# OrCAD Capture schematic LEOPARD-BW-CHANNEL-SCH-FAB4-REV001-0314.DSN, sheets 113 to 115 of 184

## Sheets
113 058_DDR4 DIMM CPU0 CHD-1: size A3; title: DDR4 DIMM CPU0 CHD-1
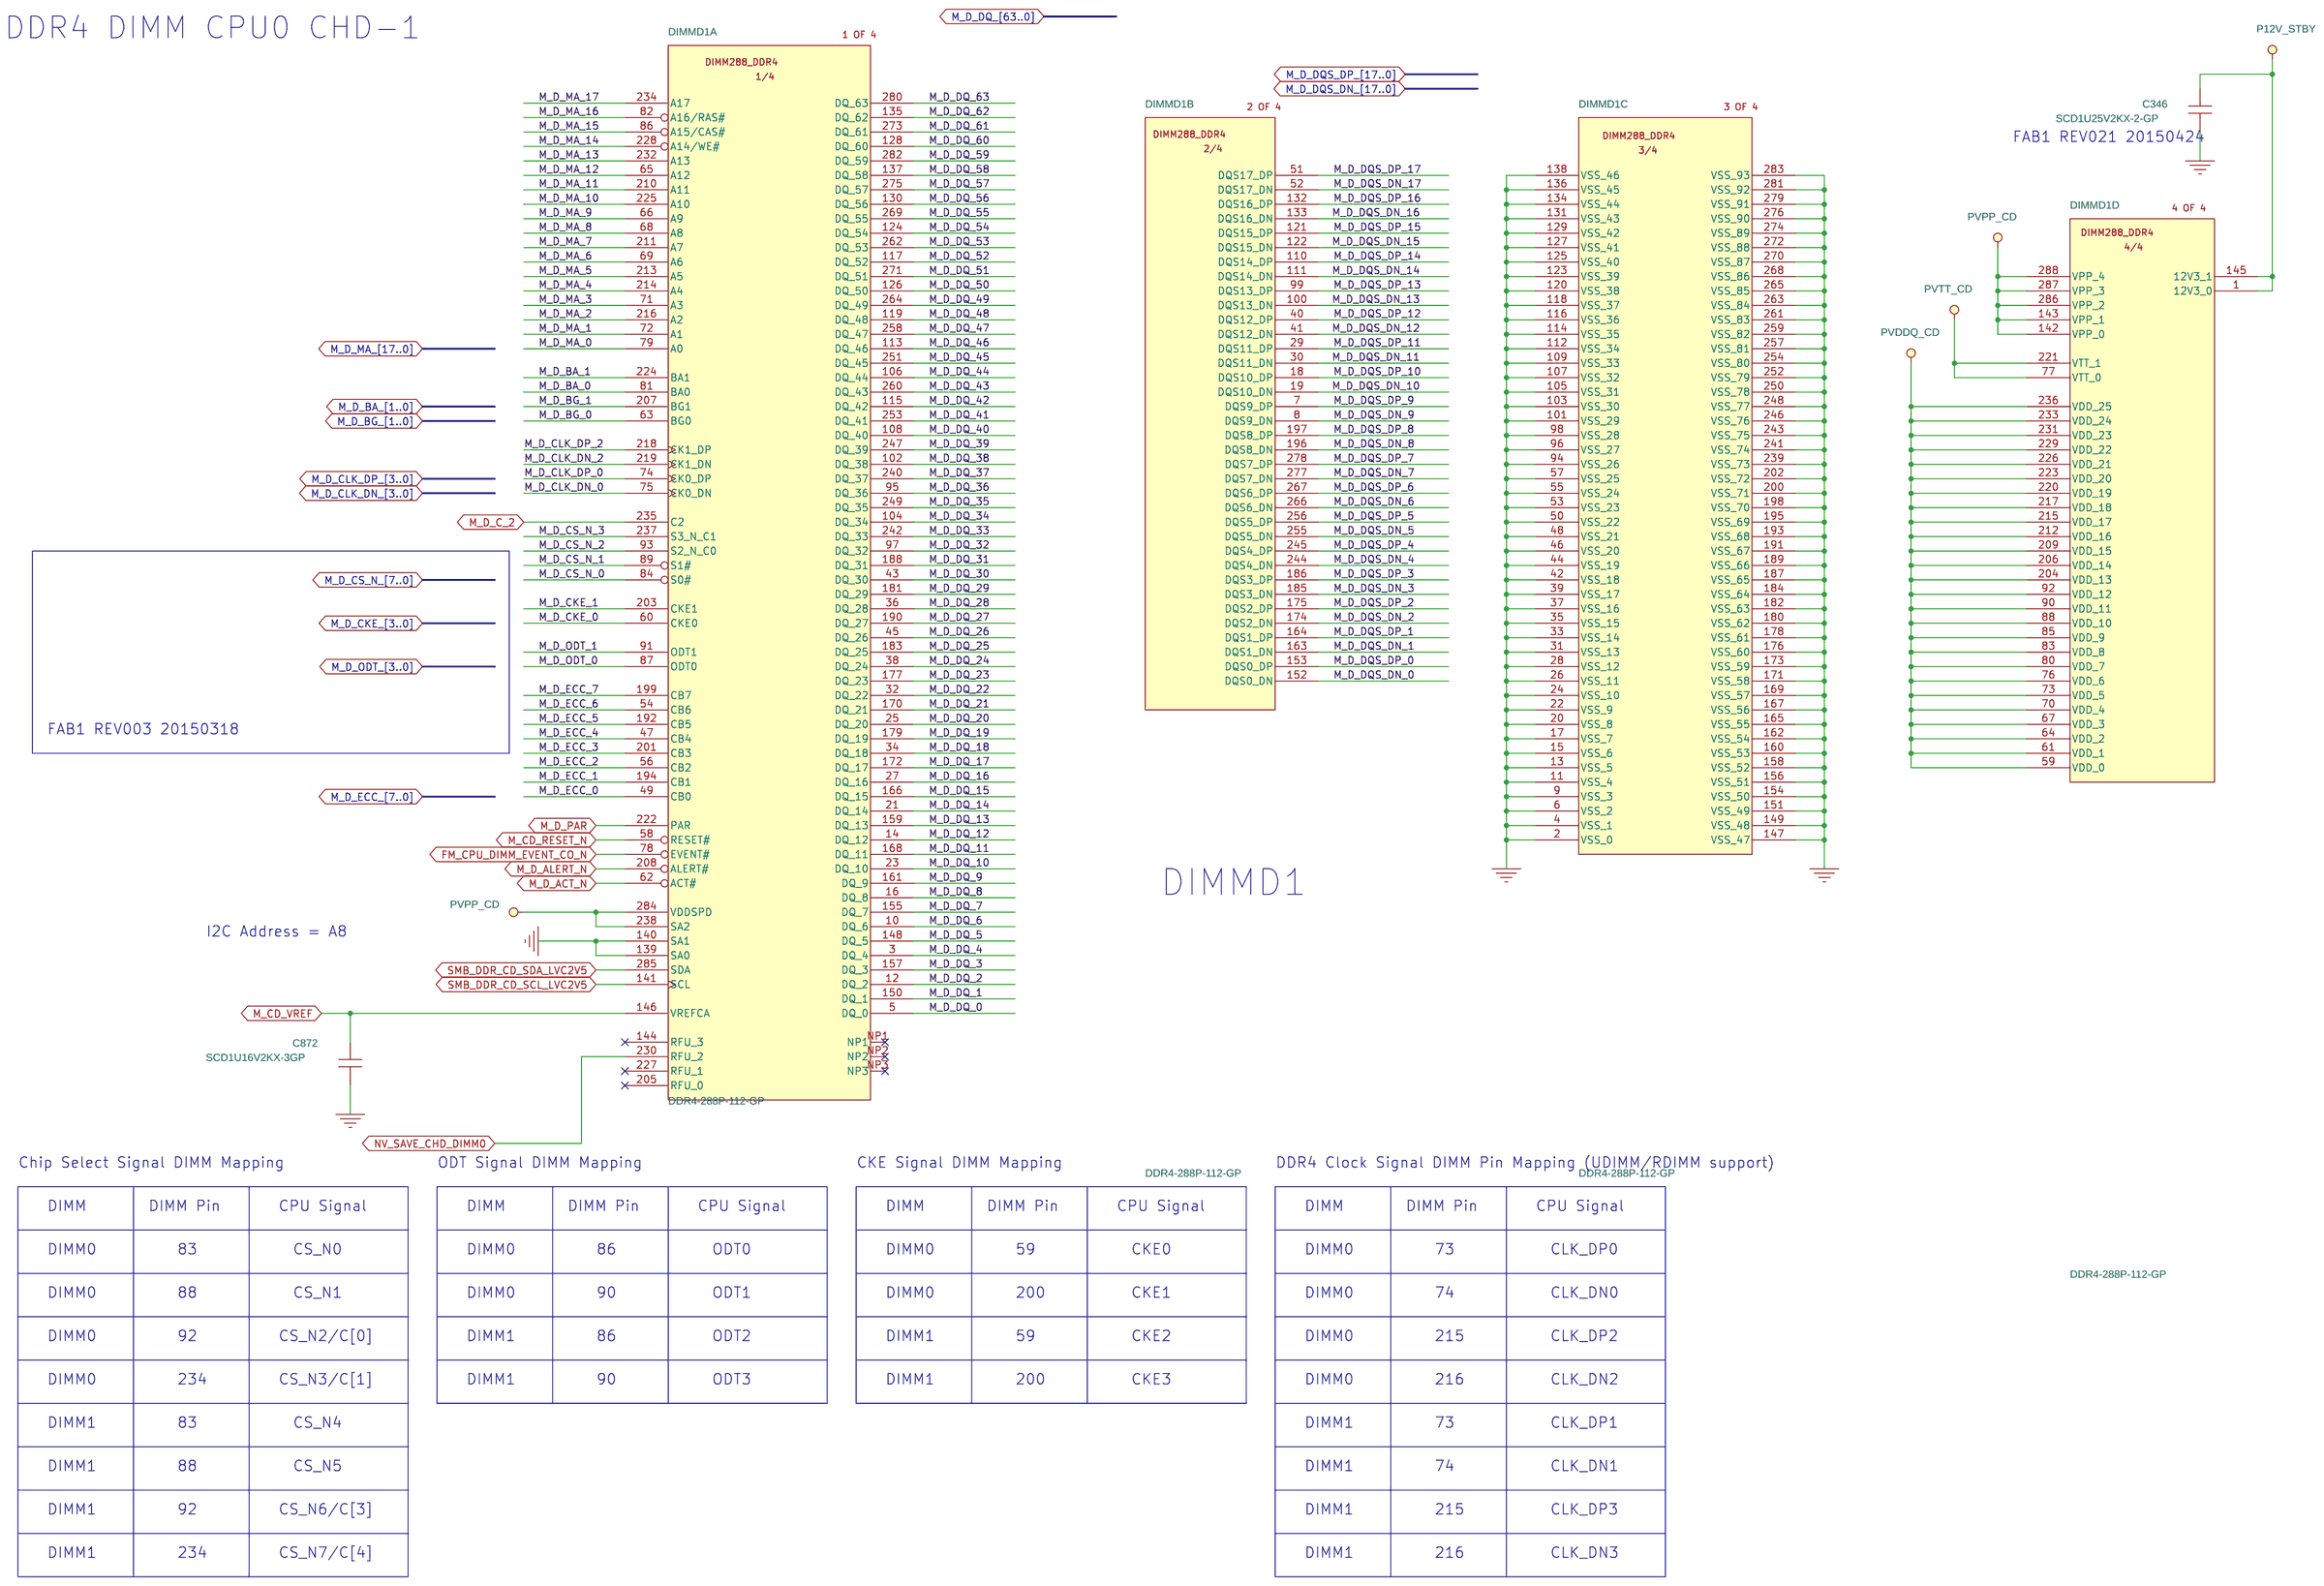
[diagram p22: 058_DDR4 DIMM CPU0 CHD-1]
114 057_DDR4 DIMM CPU0 CHC-2: size A3; title: DDR4 DIMM CPU0 CHC-2
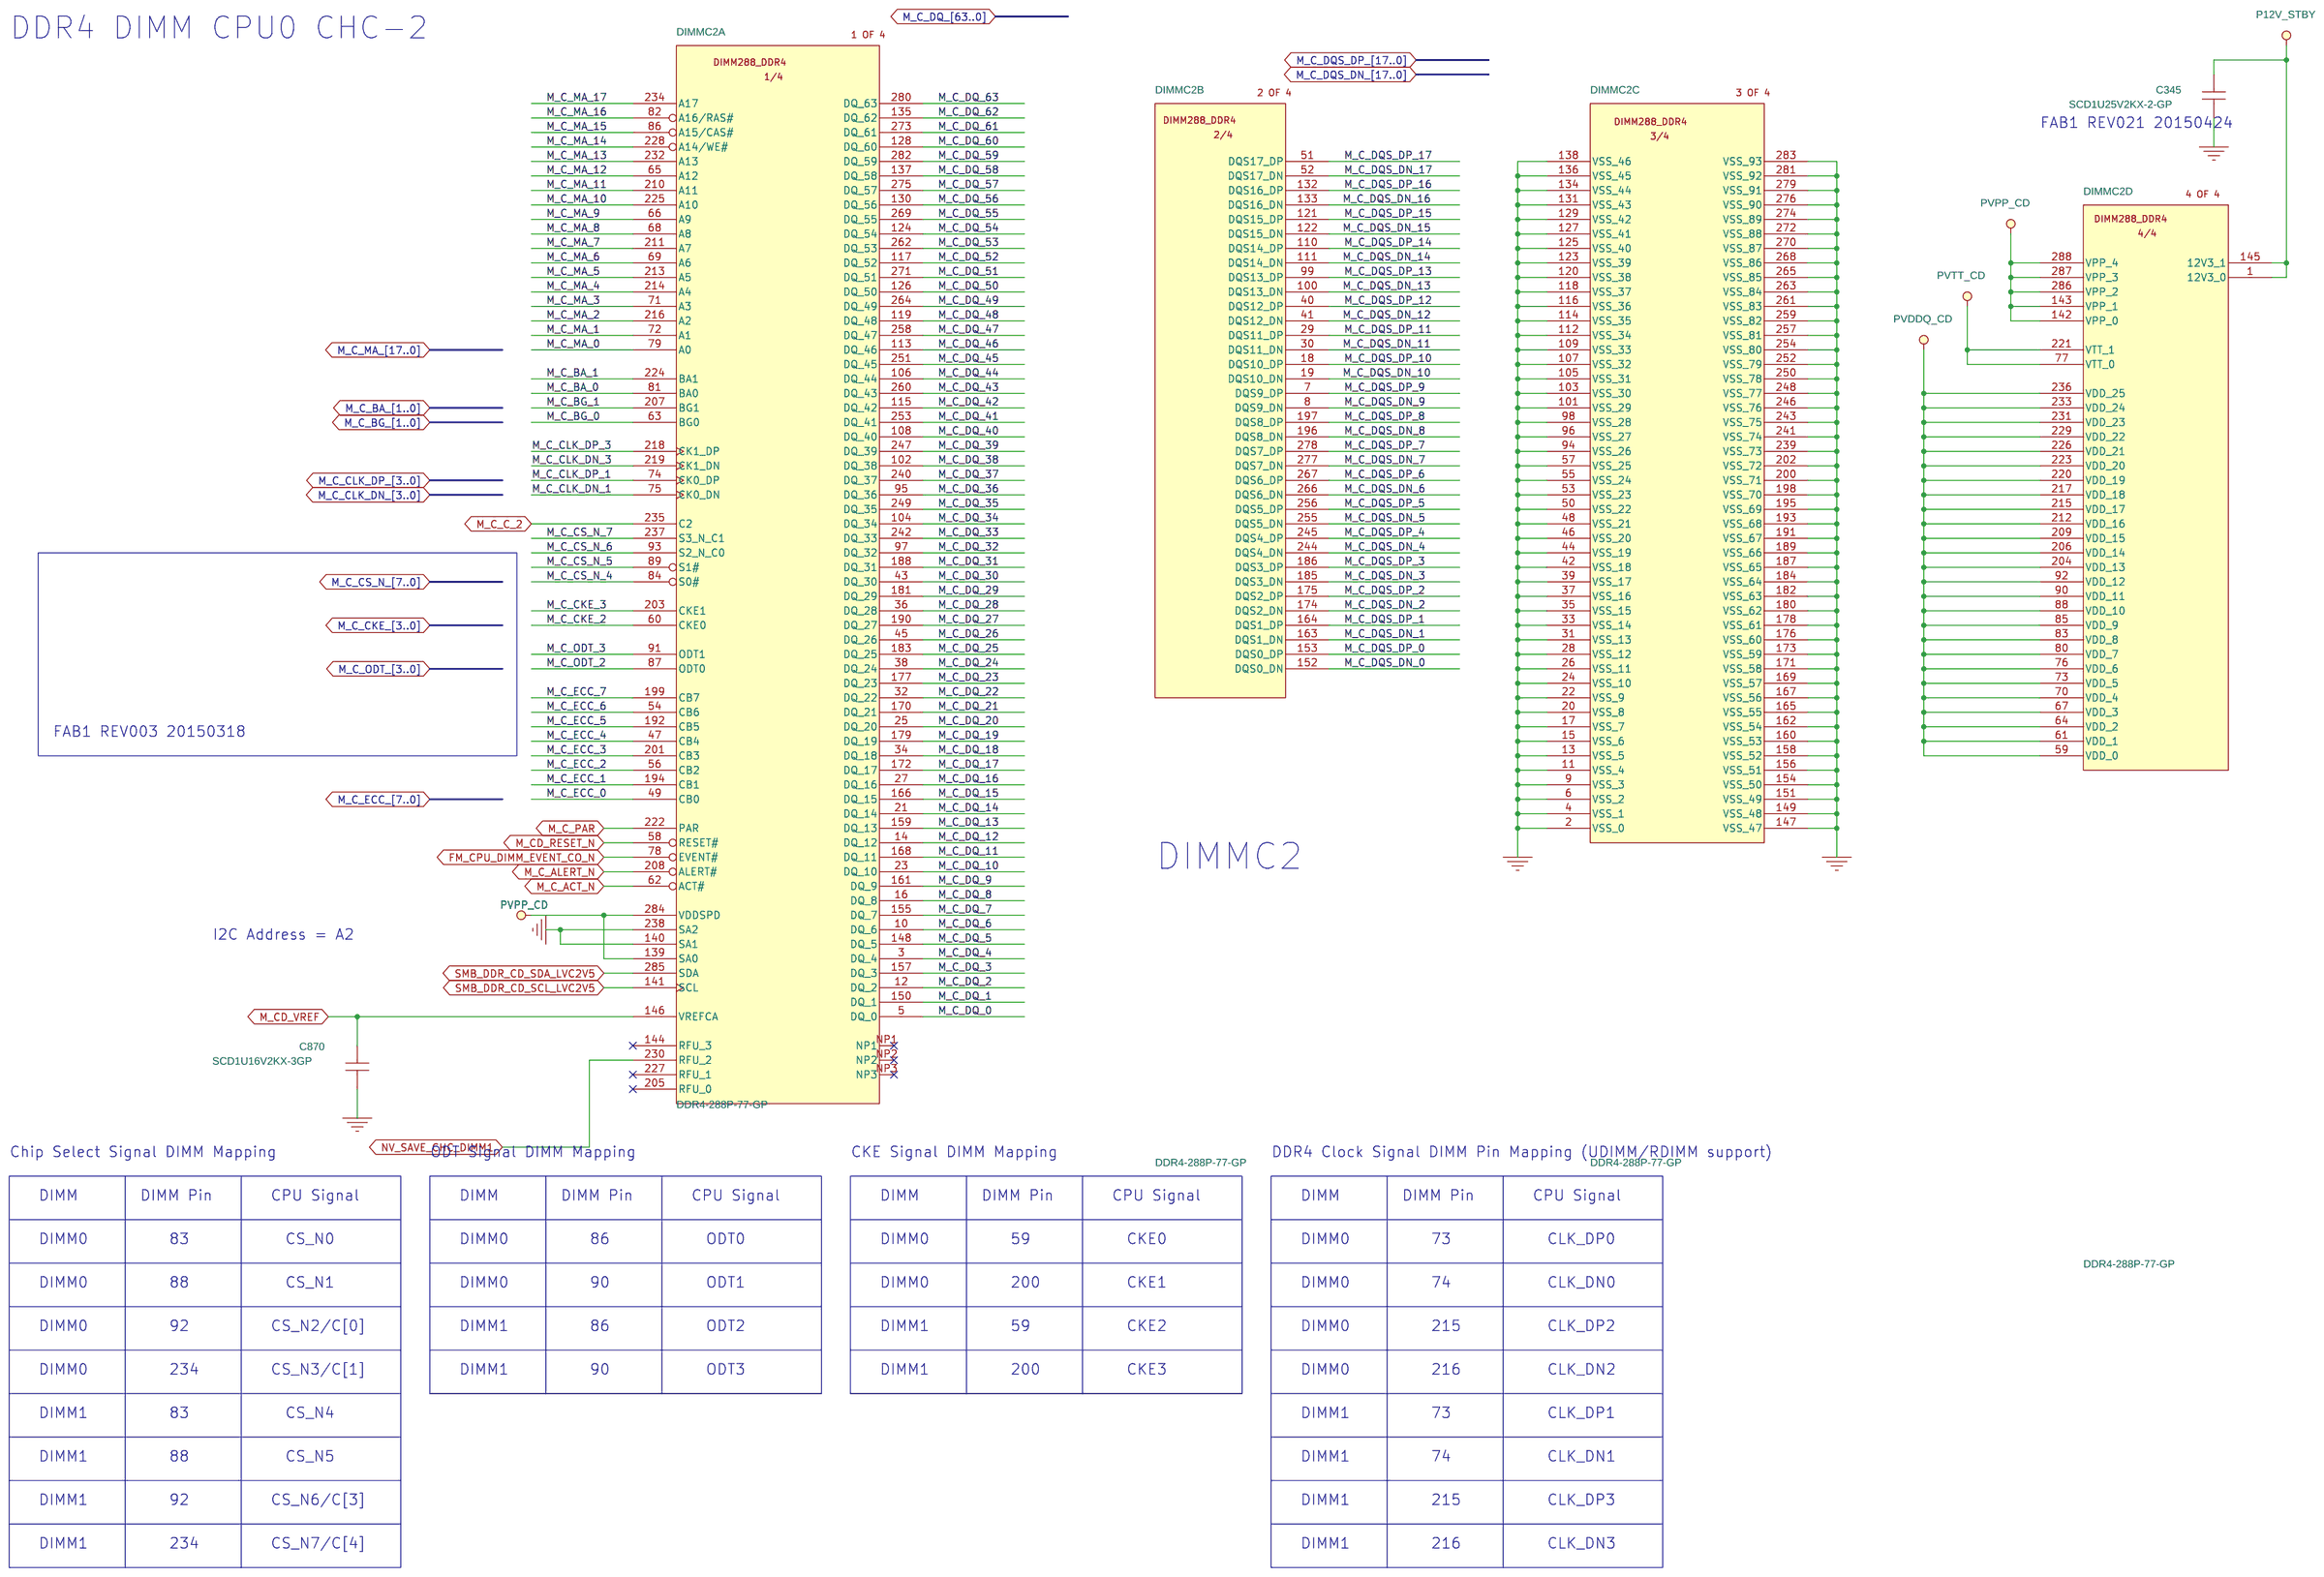
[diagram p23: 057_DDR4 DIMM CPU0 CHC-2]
115 056_DDR4 DIMM CPU0 CHC-1: size A3; title: DDR4 DIMM CPU0 CHC-1
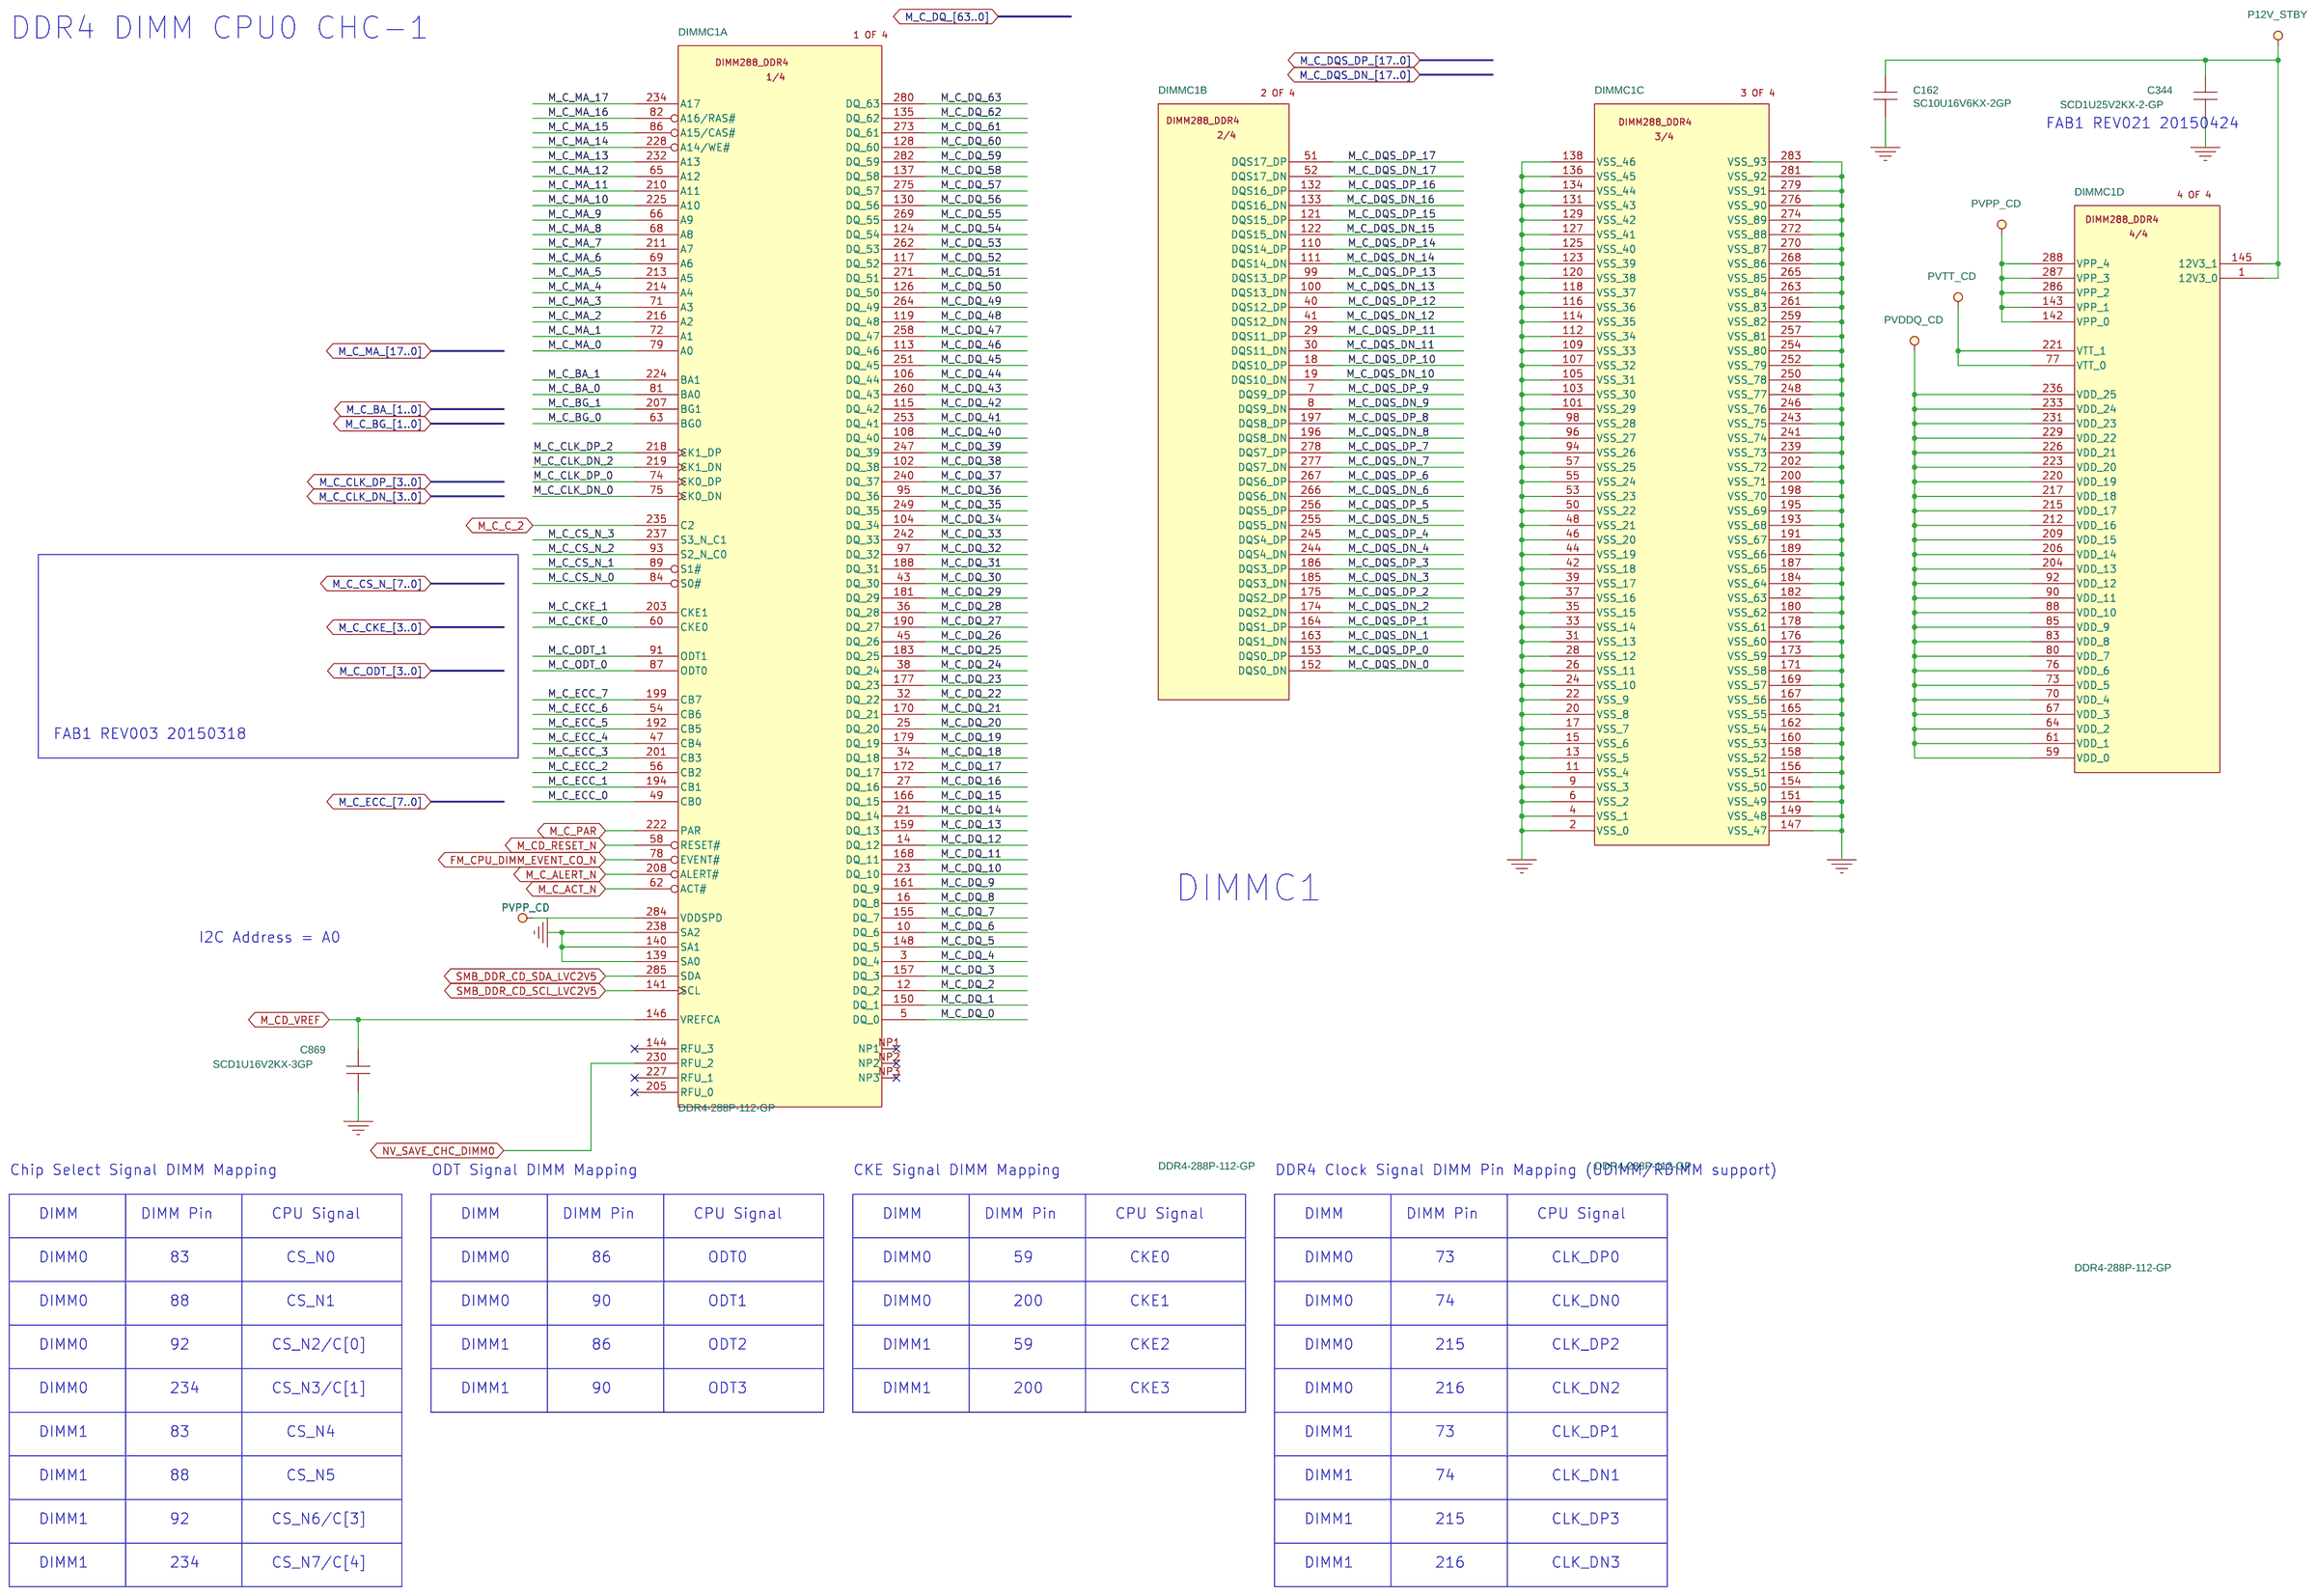
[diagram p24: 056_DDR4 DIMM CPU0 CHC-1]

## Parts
sheet 056_DDR4 DIMM CPU0 CHC-1
C162  SC10U16V6KX-2GP  [C1206H71]
C344  SCD1U25V2KX-2-GP  [C402H22]
C869  SCD1U16V2KX-3GP  [C402H22]
DIMMC1  DDR4-288P-112-GP  [10124632-0001113LF]  (sections A,B,C,D)
sheet 057_DDR4 DIMM CPU0 CHC-2
C345  SCD1U25V2KX-2-GP  [C402H22]
C870  SCD1U16V2KX-3GP  [C402H22]
DIMMC2  DDR4-288P-77-GP  [10124632-0001113LF]  (sections A,B,C,D)
sheet 058_DDR4 DIMM CPU0 CHD-1
C346  SCD1U25V2KX-2-GP  [C402H22]
C872  SCD1U16V2KX-3GP  [C402H22]
DIMMD1  DDR4-288P-112-GP  [10124632-0001113LF]  (sections A,B,C,D)

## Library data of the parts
C162 = SC10U16V6KX-2GP: CHIP CAP C 10U 16V K1206 X7R; GREENDFACTOR: R2_SA;HF_SA;G_SA;; Part Number: 78.10621.22L; Part Type: SMD-BCG; SPEC: http://wpqssvr.wistron.com.tw:7001/wpqs/servlet/COM.qpart.Attachment?PartNumber=78.10621.22L
C344-C346 = SCD1U25V2KX-2-GP: CHIP CAP C 0.1U 25V K0402 X7R; GREENDFACTOR: R2_SA;HF_SA;G_SA;; Part Number: 78.10422.2FL; Part Type: SMD-BCG4; SPEC: http://wpqssvr.wistron.com.tw:7001/wpqs/servlet/COM.qpart.Attachment?PartNumber=78.10422.2FL
C869 C870 C872 = SCD1U16V2KX-3GP: CHIP CAP C 0.1U 16V K0402 X7R; CATEGORIES: CAP_1.xV; GREENDFACTOR: R2_SA;HF_SA;G_SA;; MAIN_SOURCE: M; Part Number: 78.10421.2FL; Part Type: SMD-BCG; SPEC: http://wpqssvr.wistron.com.tw:7001/wpqs/servlet/COM.qpart.Attachment?PartNumber=78.10421.2FL
DIMMC1 DIMMD1 = DDR4-288P-112-GP: SKT DIMM DDR4 288P 10124632-0003001LF; GREENDFACTOR: R2_C;; POP?: 022.10010.0E11; Part Number: 022.10010.0B91; Part Type: SOCKET-G2; SPEC: http://wpqssvr.wistron.com.tw:7001/wpqs/servlet/COM.qpart.Attachment?PartNumber=022.10010.0B91
DIMMC2 = DDR4-288P-77-GP: SKT DIMM DDR4 288P 10124632-0001001LF; GREENDFACTOR: R2_SA;; POP?: 022.10010.0B11; Part Number: 22.10244.1A1; Part Type: SOCKET-G1; SPEC: http://wpqssvr.wistron.com.tw:7001/wpqs/servlet/COM.qpart.Attachment?PartNumber=22.10244.1A1

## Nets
GND: C162.2 C344.2 C345.2 C346.2 C869.2 C870.2 C872.2 DIMMC1.2(VSS_0) DIMMC1.4(VSS_1) DIMMC1.6(VSS_2) DIMMC1.9(VSS_3) DIMMC1.11(VSS_4) DIMMC1.13(VSS_5) DIMMC1.15(VSS_6) DIMMC1.17(VSS_7) DIMMC1.20(VSS_8) DIMMC1.22(VSS_9) DIMMC1.24(VSS_10) DIMMC1.26(VSS_11) DIMMC1.28(VSS_12) DIMMC1.31(VSS_13) DIMMC1.33(VSS_14) DIMMC1.35(VSS_15) DIMMC1.37(VSS_16) DIMMC1.39(VSS_17) DIMMC1.42(VSS_18) DIMMC1.44(VSS_19) DIMMC1.46(VSS_20) DIMMC1.48(VSS_21) DIMMC1.50(VSS_22) DIMMC1.53(VSS_23) DIMMC1.55(VSS_24) DIMMC1.57(VSS_25) DIMMC1.94(VSS_26) DIMMC1.96(VSS_27) DIMMC1.98(VSS_28) DIMMC1.101(VSS_29) DIMMC1.103(VSS_30) DIMMC1.105(VSS_31) DIMMC1.107(VSS_32) DIMMC1.109(VSS_33) DIMMC1.112(VSS_34) DIMMC1.114(VSS_35) DIMMC1.116(VSS_36) DIMMC1.118(VSS_37) DIMMC1.120(VSS_38) DIMMC1.123(VSS_39) DIMMC1.125(VSS_40) DIMMC1.127(VSS_41) DIMMC1.129(VSS_42) DIMMC1.131(VSS_43) DIMMC1.134(VSS_44) DIMMC1.136(VSS_45) DIMMC1.138(VSS_46) DIMMC1.139(SA0) DIMMC1.140(SA1) DIMMC1.147(VSS_47) DIMMC1.149(VSS_48) DIMMC1.151(VSS_49) DIMMC1.154(VSS_50) DIMMC1.156(VSS_51) DIMMC1.158(VSS_52) DIMMC1.160(VSS_53) DIMMC1.162(VSS_54) DIMMC1.165(VSS_55) DIMMC1.167(VSS_56) DIMMC1.169(VSS_57) DIMMC1.171(VSS_58) DIMMC1.173(VSS_59) DIMMC1.176(VSS_60) DIMMC1.178(VSS_61) DIMMC1.180(VSS_62) DIMMC1.182(VSS_63) DIMMC1.184(VSS_64) DIMMC1.187(VSS_65) DIMMC1.189(VSS_66) DIMMC1.191(VSS_67) DIMMC1.193(VSS_68) DIMMC1.195(VSS_69) DIMMC1.198(VSS_70) DIMMC1.200(VSS_71) DIMMC1.202(VSS_72) DIMMC1.238(SA2) DIMMC1.239(VSS_73) DIMMC1.241(VSS_74) DIMMC1.243(VSS_75) DIMMC1.246(VSS_76) DIMMC1.248(VSS_77) DIMMC1.250(VSS_78) DIMMC1.252(VSS_79) DIMMC1.254(VSS_80) DIMMC1.257(VSS_81) DIMMC1.259(VSS_82) DIMMC1.261(VSS_83) DIMMC1.263(VSS_84) DIMMC1.265(VSS_85) DIMMC1.268(VSS_86) DIMMC1.270(VSS_87) DIMMC1.272(VSS_88) DIMMC1.274(VSS_89) DIMMC1.276(VSS_90) DIMMC1.279(VSS_91) DIMMC1.281(VSS_92) DIMMC1.283(VSS_93) DIMMC2.2(VSS_0) DIMMC2.4(VSS_1) DIMMC2.6(VSS_2) DIMMC2.9(VSS_3) DIMMC2.11(VSS_4) DIMMC2.13(VSS_5) DIMMC2.15(VSS_6) DIMMC2.17(VSS_7) DIMMC2.20(VSS_8) DIMMC2.22(VSS_9) DIMMC2.24(VSS_10) DIMMC2.26(VSS_11) DIMMC2.28(VSS_12) DIMMC2.31(VSS_13) DIMMC2.33(VSS_14) DIMMC2.35(VSS_15) DIMMC2.37(VSS_16) DIMMC2.39(VSS_17) DIMMC2.42(VSS_18) DIMMC2.44(VSS_19) DIMMC2.46(VSS_20) DIMMC2.48(VSS_21) DIMMC2.50(VSS_22) DIMMC2.53(VSS_23) DIMMC2.55(VSS_24) DIMMC2.57(VSS_25) DIMMC2.94(VSS_26) DIMMC2.96(VSS_27) DIMMC2.98(VSS_28) DIMMC2.101(VSS_29) DIMMC2.103(VSS_30) DIMMC2.105(VSS_31) DIMMC2.107(VSS_32) DIMMC2.109(VSS_33) DIMMC2.112(VSS_34) DIMMC2.114(VSS_35) DIMMC2.116(VSS_36) DIMMC2.118(VSS_37) DIMMC2.120(VSS_38) DIMMC2.123(VSS_39) DIMMC2.125(VSS_40) DIMMC2.127(VSS_41) DIMMC2.129(VSS_42) DIMMC2.131(VSS_43) DIMMC2.134(VSS_44) DIMMC2.136(VSS_45) DIMMC2.138(VSS_46) DIMMC2.140(SA1) DIMMC2.147(VSS_47) DIMMC2.149(VSS_48) DIMMC2.151(VSS_49) DIMMC2.154(VSS_50) DIMMC2.156(VSS_51) DIMMC2.158(VSS_52) DIMMC2.160(VSS_53) DIMMC2.162(VSS_54) DIMMC2.165(VSS_55) DIMMC2.167(VSS_56) DIMMC2.169(VSS_57) DIMMC2.171(VSS_58) DIMMC2.173(VSS_59) DIMMC2.176(VSS_60) DIMMC2.178(VSS_61) DIMMC2.180(VSS_62) DIMMC2.182(VSS_63) DIMMC2.184(VSS_64) DIMMC2.187(VSS_65) DIMMC2.189(VSS_66) DIMMC2.191(VSS_67) DIMMC2.193(VSS_68) DIMMC2.195(VSS_69) DIMMC2.198(VSS_70) DIMMC2.200(VSS_71) DIMMC2.202(VSS_72) DIMMC2.238(SA2) DIMMC2.239(VSS_73) DIMMC2.241(VSS_74) DIMMC2.243(VSS_75) DIMMC2.246(VSS_76) DIMMC2.248(VSS_77) DIMMC2.250(VSS_78) DIMMC2.252(VSS_79) DIMMC2.254(VSS_80) DIMMC2.257(VSS_81) DIMMC2.259(VSS_82) DIMMC2.261(VSS_83) DIMMC2.263(VSS_84) DIMMC2.265(VSS_85) DIMMC2.268(VSS_86) DIMMC2.270(VSS_87) DIMMC2.272(VSS_88) DIMMC2.274(VSS_89) DIMMC2.276(VSS_90) DIMMC2.279(VSS_91) DIMMC2.281(VSS_92) DIMMC2.283(VSS_93) DIMMD1.2(VSS_0) DIMMD1.4(VSS_1) DIMMD1.6(VSS_2) DIMMD1.9(VSS_3) DIMMD1.11(VSS_4) DIMMD1.13(VSS_5) DIMMD1.15(VSS_6) DIMMD1.17(VSS_7) DIMMD1.20(VSS_8) DIMMD1.22(VSS_9) DIMMD1.24(VSS_10) DIMMD1.26(VSS_11) DIMMD1.28(VSS_12) DIMMD1.31(VSS_13) DIMMD1.33(VSS_14) DIMMD1.35(VSS_15) DIMMD1.37(VSS_16) DIMMD1.39(VSS_17) DIMMD1.42(VSS_18) DIMMD1.44(VSS_19) DIMMD1.46(VSS_20) DIMMD1.48(VSS_21) DIMMD1.50(VSS_22) DIMMD1.53(VSS_23) DIMMD1.55(VSS_24) DIMMD1.57(VSS_25) DIMMD1.94(VSS_26) DIMMD1.96(VSS_27) DIMMD1.98(VSS_28) DIMMD1.101(VSS_29) DIMMD1.103(VSS_30) DIMMD1.105(VSS_31) DIMMD1.107(VSS_32) DIMMD1.109(VSS_33) DIMMD1.112(VSS_34) DIMMD1.114(VSS_35) DIMMD1.116(VSS_36) DIMMD1.118(VSS_37) DIMMD1.120(VSS_38) DIMMD1.123(VSS_39) DIMMD1.125(VSS_40) DIMMD1.127(VSS_41) DIMMD1.129(VSS_42) DIMMD1.131(VSS_43) DIMMD1.134(VSS_44) DIMMD1.136(VSS_45) DIMMD1.138(VSS_46) DIMMD1.139(SA0) DIMMD1.140(SA1) DIMMD1.147(VSS_47) DIMMD1.149(VSS_48) DIMMD1.151(VSS_49) DIMMD1.154(VSS_50) DIMMD1.156(VSS_51) DIMMD1.158(VSS_52) DIMMD1.160(VSS_53) DIMMD1.162(VSS_54) DIMMD1.165(VSS_55) DIMMD1.167(VSS_56) DIMMD1.169(VSS_57) DIMMD1.171(VSS_58) DIMMD1.173(VSS_59) DIMMD1.176(VSS_60) DIMMD1.178(VSS_61) DIMMD1.180(VSS_62) DIMMD1.182(VSS_63) DIMMD1.184(VSS_64) DIMMD1.187(VSS_65) DIMMD1.189(VSS_66) DIMMD1.191(VSS_67) DIMMD1.193(VSS_68) DIMMD1.195(VSS_69) DIMMD1.198(VSS_70) DIMMD1.200(VSS_71) DIMMD1.202(VSS_72) DIMMD1.239(VSS_73) DIMMD1.241(VSS_74) DIMMD1.243(VSS_75) DIMMD1.246(VSS_76) DIMMD1.248(VSS_77) DIMMD1.250(VSS_78) DIMMD1.252(VSS_79) DIMMD1.254(VSS_80) DIMMD1.257(VSS_81) DIMMD1.259(VSS_82) DIMMD1.261(VSS_83) DIMMD1.263(VSS_84) DIMMD1.265(VSS_85) DIMMD1.268(VSS_86) DIMMD1.270(VSS_87) DIMMD1.272(VSS_88) DIMMD1.274(VSS_89) DIMMD1.276(VSS_90) DIMMD1.279(VSS_91) DIMMD1.281(VSS_92) DIMMD1.283(VSS_93) ; also on sheet 1 2 3 4 5 6 7 8 9 10 11 12 13 14 15 16 17 18 19 20 21 22 23 24 25 26 27 28 29 30 31 32 33 34 35 36 37 38 39 44 46 47 49 50 51 52 53 54 55 56 57 58 59 60 61 62 63 64 65 66 69 70 71 73 74 75 76 78 79 80 81 82 83 84 86 87 88 89 90 91 92 93 94 95 96 97 98 99 100 101 102 103 104 105 106 107 108 109 110 111 112 116 117 118 119 128 129 138 139 159 160 161 166 168 169 170 171 172 173 174 175 176 177 180 181 182 183 184
P12V_STBY: C162.1 C344.1 C345.1 C346.1 DIMMC1.1(12V3_0) DIMMC1.145(12V3_1) DIMMC2.1(12V3_0) DIMMC2.145(12V3_1) DIMMD1.1(12V3_0) DIMMD1.145(12V3_1) ; also on sheet 2 3 4 7 9 10 11 12 13 17 18 22 23 27 28 32 36 59 60 75 95 104 105 106 107 108 109 110 111 112 116 117 118 119
PVDDQ_CD: DIMMC1.59(VDD_0) DIMMC1.61(VDD_1) DIMMC1.64(VDD_2) DIMMC1.67(VDD_3) DIMMC1.70(VDD_4) DIMMC1.73(VDD_5) DIMMC1.76(VDD_6) DIMMC1.80(VDD_7) DIMMC1.83(VDD_8) DIMMC1.85(VDD_9) DIMMC1.88(VDD_10) DIMMC1.90(VDD_11) DIMMC1.92(VDD_12) DIMMC1.204(VDD_13) DIMMC1.206(VDD_14) DIMMC1.209(VDD_15) DIMMC1.212(VDD_16) DIMMC1.215(VDD_17) DIMMC1.217(VDD_18) DIMMC1.220(VDD_19) DIMMC1.223(VDD_20) DIMMC1.226(VDD_21) DIMMC1.229(VDD_22) DIMMC1.231(VDD_23) DIMMC1.233(VDD_24) DIMMC1.236(VDD_25) DIMMC2.59(VDD_0) DIMMC2.61(VDD_1) DIMMC2.64(VDD_2) DIMMC2.67(VDD_3) DIMMC2.70(VDD_4) DIMMC2.73(VDD_5) DIMMC2.76(VDD_6) DIMMC2.80(VDD_7) DIMMC2.83(VDD_8) DIMMC2.85(VDD_9) DIMMC2.88(VDD_10) DIMMC2.90(VDD_11) DIMMC2.92(VDD_12) DIMMC2.204(VDD_13) DIMMC2.206(VDD_14) DIMMC2.209(VDD_15) DIMMC2.212(VDD_16) DIMMC2.215(VDD_17) DIMMC2.217(VDD_18) DIMMC2.220(VDD_19) DIMMC2.223(VDD_20) DIMMC2.226(VDD_21) DIMMC2.229(VDD_22) DIMMC2.231(VDD_23) DIMMC2.233(VDD_24) DIMMC2.236(VDD_25) DIMMD1.59(VDD_0) DIMMD1.61(VDD_1) DIMMD1.64(VDD_2) DIMMD1.67(VDD_3) DIMMD1.70(VDD_4) DIMMD1.73(VDD_5) DIMMD1.76(VDD_6) DIMMD1.80(VDD_7) DIMMD1.83(VDD_8) DIMMD1.85(VDD_9) DIMMD1.88(VDD_10) DIMMD1.90(VDD_11) DIMMD1.92(VDD_12) DIMMD1.204(VDD_13) DIMMD1.206(VDD_14) DIMMD1.209(VDD_15) DIMMD1.212(VDD_16) DIMMD1.215(VDD_17) DIMMD1.217(VDD_18) DIMMD1.220(VDD_19) DIMMD1.223(VDD_20) DIMMD1.226(VDD_21) DIMMD1.229(VDD_22) DIMMD1.231(VDD_23) DIMMD1.233(VDD_24) DIMMD1.236(VDD_25) ; also on sheet 23 25 45 97 112 130 139
FM_CPU_DIMM_EVENT_CO_N: DIMMC1.78(EVENT#) DIMMC2.78(EVENT#) DIMMD1.78(EVENT#) ; also on sheet 98 104 105 106 107 108 109 110 111 112 116 117 118 119
M_C_ACT_N: DIMMC1.62(ACT#) DIMMC2.62(ACT#) ; also on sheet 135
M_C_ALERT_N: DIMMC1.208(ALERT#) DIMMC2.208(ALERT#) ; also on sheet 135
M_C_BA_0: DIMMC1.81(BA0) DIMMC2.81(BA0) ; also on sheet 135
M_C_BA_1: DIMMC1.224(BA1) DIMMC2.224(BA1) ; also on sheet 135
M_C_BG_0: DIMMC1.63(BG0) DIMMC2.63(BG0) ; also on sheet 135
M_C_BG_1: DIMMC1.207(BG1) DIMMC2.207(BG1) ; also on sheet 135
M_C_C_2: DIMMC1.235(C2) DIMMC2.235(C2) ; also on sheet 135
M_C_CKE_0: DIMMC1.60(CKE0) ; also on sheet 135
M_C_CKE_1: DIMMC1.203(CKE1) ; also on sheet 135
M_C_CKE_2: DIMMC2.60(CKE0) ; also on sheet 135
M_C_CKE_3: DIMMC2.203(CKE1) ; also on sheet 135
M_C_CLK_DN_0: DIMMC1.75(CK0_DN) ; also on sheet 135
M_C_CLK_DN_1: DIMMC2.75(CK0_DN) ; also on sheet 135
M_C_CLK_DN_2: DIMMC1.219(CK1_DN) ; also on sheet 135
M_C_CLK_DN_3: DIMMC2.219(CK1_DN) ; also on sheet 135
M_C_CLK_DP_0: DIMMC1.74(CK0_DP) ; also on sheet 135
M_C_CLK_DP_1: DIMMC2.74(CK0_DP) ; also on sheet 135
M_C_CLK_DP_2: DIMMC1.218(CK1_DP) ; also on sheet 135
M_C_CLK_DP_3: DIMMC2.218(CK1_DP) ; also on sheet 135
M_C_CS_N_0: DIMMC1.84(S0#) ; also on sheet 135
M_C_CS_N_1: DIMMC1.89(S1#) ; also on sheet 135
M_C_CS_N_2: DIMMC1.93(S2_N_C0) ; also on sheet 135
M_C_CS_N_3: DIMMC1.237(S3_N_C1) ; also on sheet 135
M_C_CS_N_4: DIMMC2.84(S0#) ; also on sheet 135
M_C_CS_N_5: DIMMC2.89(S1#) ; also on sheet 135
M_C_CS_N_6: DIMMC2.93(S2_N_C0) ; also on sheet 135
M_C_CS_N_7: DIMMC2.237(S3_N_C1) ; also on sheet 135
M_C_DQ_0: DIMMC1.5(DQ_0) DIMMC2.5(DQ_0) ; also on sheet 135
M_C_DQ_1: DIMMC1.150(DQ_1) DIMMC2.150(DQ_1) ; also on sheet 135
M_C_DQ_2: DIMMC1.12(DQ_2) DIMMC2.12(DQ_2) ; also on sheet 135
M_C_DQ_3: DIMMC1.157(DQ_3) DIMMC2.157(DQ_3) ; also on sheet 135
M_C_DQ_4: DIMMC1.3(DQ_4) DIMMC2.3(DQ_4) ; also on sheet 135
M_C_DQ_5: DIMMC1.148(DQ_5) DIMMC2.148(DQ_5) ; also on sheet 135
M_C_DQ_6: DIMMC1.10(DQ_6) DIMMC2.10(DQ_6) ; also on sheet 135
M_C_DQ_7: DIMMC1.155(DQ_7) DIMMC2.155(DQ_7) ; also on sheet 135
M_C_DQ_8: DIMMC1.16(DQ_8) DIMMC2.16(DQ_8) ; also on sheet 135
M_C_DQ_9: DIMMC1.161(DQ_9) DIMMC2.161(DQ_9) ; also on sheet 135
M_C_DQ_10: DIMMC1.23(DQ_10) DIMMC2.23(DQ_10) ; also on sheet 135
M_C_DQ_11: DIMMC1.168(DQ_11) DIMMC2.168(DQ_11) ; also on sheet 135
M_C_DQ_12: DIMMC1.14(DQ_12) DIMMC2.14(DQ_12) ; also on sheet 135
M_C_DQ_13: DIMMC1.159(DQ_13) DIMMC2.159(DQ_13) ; also on sheet 135
M_C_DQ_14: DIMMC1.21(DQ_14) DIMMC2.21(DQ_14) ; also on sheet 135
M_C_DQ_15: DIMMC1.166(DQ_15) DIMMC2.166(DQ_15) ; also on sheet 135
M_C_DQ_16: DIMMC1.27(DQ_16) DIMMC2.27(DQ_16) ; also on sheet 135
M_C_DQ_17: DIMMC1.172(DQ_17) DIMMC2.172(DQ_17) ; also on sheet 135
M_C_DQ_18: DIMMC1.34(DQ_18) DIMMC2.34(DQ_18) ; also on sheet 135
M_C_DQ_19: DIMMC1.179(DQ_19) DIMMC2.179(DQ_19) ; also on sheet 135
M_C_DQ_20: DIMMC1.25(DQ_20) DIMMC2.25(DQ_20) ; also on sheet 135
M_C_DQ_21: DIMMC1.170(DQ_21) DIMMC2.170(DQ_21) ; also on sheet 135
M_C_DQ_22: DIMMC1.32(DQ_22) DIMMC2.32(DQ_22) ; also on sheet 135
M_C_DQ_23: DIMMC1.177(DQ_23) DIMMC2.177(DQ_23) ; also on sheet 135
M_C_DQ_24: DIMMC1.38(DQ_24) DIMMC2.38(DQ_24) ; also on sheet 135
M_C_DQ_25: DIMMC1.183(DQ_25) DIMMC2.183(DQ_25) ; also on sheet 135
M_C_DQ_26: DIMMC1.45(DQ_26) DIMMC2.45(DQ_26) ; also on sheet 135
M_C_DQ_27: DIMMC1.190(DQ_27) DIMMC2.190(DQ_27) ; also on sheet 135
M_C_DQ_28: DIMMC1.36(DQ_28) DIMMC2.36(DQ_28) ; also on sheet 135
M_C_DQ_29: DIMMC1.181(DQ_29) DIMMC2.181(DQ_29) ; also on sheet 135
M_C_DQ_30: DIMMC1.43(DQ_30) DIMMC2.43(DQ_30) ; also on sheet 135
M_C_DQ_31: DIMMC1.188(DQ_31) DIMMC2.188(DQ_31) ; also on sheet 135
M_C_DQ_32: DIMMC1.97(DQ_32) DIMMC2.97(DQ_32) ; also on sheet 135
M_C_DQ_33: DIMMC1.242(DQ_33) DIMMC2.242(DQ_33) ; also on sheet 135
M_C_DQ_34: DIMMC1.104(DQ_34) DIMMC2.104(DQ_34) ; also on sheet 135
M_C_DQ_35: DIMMC1.249(DQ_35) DIMMC2.249(DQ_35) ; also on sheet 135
M_C_DQ_36: DIMMC1.95(DQ_36) DIMMC2.95(DQ_36) ; also on sheet 135
M_C_DQ_37: DIMMC1.240(DQ_37) DIMMC2.240(DQ_37) ; also on sheet 135
M_C_DQ_38: DIMMC1.102(DQ_38) DIMMC2.102(DQ_38) ; also on sheet 135
M_C_DQ_39: DIMMC1.247(DQ_39) DIMMC2.247(DQ_39) ; also on sheet 135
M_C_DQ_40: DIMMC1.108(DQ_40) DIMMC2.108(DQ_40) ; also on sheet 135
M_C_DQ_41: DIMMC1.253(DQ_41) DIMMC2.253(DQ_41) ; also on sheet 135
M_C_DQ_42: DIMMC1.115(DQ_42) DIMMC2.115(DQ_42) ; also on sheet 135
M_C_DQ_43: DIMMC1.260(DQ_43) DIMMC2.260(DQ_43) ; also on sheet 135
M_C_DQ_44: DIMMC1.106(DQ_44) DIMMC2.106(DQ_44) ; also on sheet 135
M_C_DQ_45: DIMMC1.251(DQ_45) DIMMC2.251(DQ_45) ; also on sheet 135
M_C_DQ_46: DIMMC1.113(DQ_46) DIMMC2.113(DQ_46) ; also on sheet 135
M_C_DQ_47: DIMMC1.258(DQ_47) DIMMC2.258(DQ_47) ; also on sheet 135
M_C_DQ_48: DIMMC1.119(DQ_48) DIMMC2.119(DQ_48) ; also on sheet 135
M_C_DQ_49: DIMMC1.264(DQ_49) DIMMC2.264(DQ_49) ; also on sheet 135
M_C_DQ_50: DIMMC1.126(DQ_50) DIMMC2.126(DQ_50) ; also on sheet 135
M_C_DQ_51: DIMMC1.271(DQ_51) DIMMC2.271(DQ_51) ; also on sheet 135
M_C_DQ_52: DIMMC1.117(DQ_52) DIMMC2.117(DQ_52) ; also on sheet 135
M_C_DQ_53: DIMMC1.262(DQ_53) DIMMC2.262(DQ_53) ; also on sheet 135
M_C_DQ_54: DIMMC1.124(DQ_54) DIMMC2.124(DQ_54) ; also on sheet 135
M_C_DQ_55: DIMMC1.269(DQ_55) DIMMC2.269(DQ_55) ; also on sheet 135
M_C_DQ_56: DIMMC1.130(DQ_56) DIMMC2.130(DQ_56) ; also on sheet 135
M_C_DQ_57: DIMMC1.275(DQ_57) DIMMC2.275(DQ_57) ; also on sheet 135
M_C_DQ_58: DIMMC1.137(DQ_58) DIMMC2.137(DQ_58) ; also on sheet 135
M_C_DQ_59: DIMMC1.282(DQ_59) DIMMC2.282(DQ_59) ; also on sheet 135
M_C_DQ_60: DIMMC1.128(DQ_60) DIMMC2.128(DQ_60) ; also on sheet 135
M_C_DQ_61: DIMMC1.273(DQ_61) DIMMC2.273(DQ_61) ; also on sheet 135
M_C_DQ_62: DIMMC1.135(DQ_62) DIMMC2.135(DQ_62) ; also on sheet 135
M_C_DQ_63: DIMMC1.280(DQ_63) DIMMC2.280(DQ_63) ; also on sheet 135
M_C_DQS_DN_0: DIMMC1.152(DQS0_DN) DIMMC2.152(DQS0_DN) ; also on sheet 135
M_C_DQS_DN_1: DIMMC1.163(DQS1_DN) DIMMC2.163(DQS1_DN) ; also on sheet 135
M_C_DQS_DN_2: DIMMC1.174(DQS2_DN) DIMMC2.174(DQS2_DN) ; also on sheet 135
M_C_DQS_DN_3: DIMMC1.185(DQS3_DN) DIMMC2.185(DQS3_DN) ; also on sheet 135
M_C_DQS_DN_4: DIMMC1.244(DQS4_DN) DIMMC2.244(DQS4_DN) ; also on sheet 135
M_C_DQS_DN_5: DIMMC1.255(DQS5_DN) DIMMC2.255(DQS5_DN) ; also on sheet 135
M_C_DQS_DN_6: DIMMC1.266(DQS6_DN) DIMMC2.266(DQS6_DN) ; also on sheet 135
M_C_DQS_DN_7: DIMMC1.277(DQS7_DN) DIMMC2.277(DQS7_DN) ; also on sheet 135
M_C_DQS_DN_8: DIMMC1.196(DQS8_DN) DIMMC2.196(DQS8_DN) ; also on sheet 135
M_C_DQS_DN_9: DIMMC1.8(DQS9_DN) DIMMC2.8(DQS9_DN) ; also on sheet 135
M_C_DQS_DN_10: DIMMC1.19(DQS10_DN) DIMMC2.19(DQS10_DN) ; also on sheet 135
M_C_DQS_DN_11: DIMMC1.30(DQS11_DN) DIMMC2.30(DQS11_DN) ; also on sheet 135
M_C_DQS_DN_12: DIMMC1.41(DQS12_DN) DIMMC2.41(DQS12_DN) ; also on sheet 135
M_C_DQS_DN_13: DIMMC1.100(DQS13_DN) DIMMC2.100(DQS13_DN) ; also on sheet 135
M_C_DQS_DN_14: DIMMC1.111(DQS14_DN) DIMMC2.111(DQS14_DN) ; also on sheet 135
M_C_DQS_DN_15: DIMMC1.122(DQS15_DN) DIMMC2.122(DQS15_DN) ; also on sheet 135
M_C_DQS_DN_16: DIMMC1.133(DQS16_DN) DIMMC2.133(DQS16_DN) ; also on sheet 135
M_C_DQS_DN_17: DIMMC1.52(DQS17_DN) DIMMC2.52(DQS17_DN) ; also on sheet 135
M_C_DQS_DP_0: DIMMC1.153(DQS0_DP) DIMMC2.153(DQS0_DP) ; also on sheet 135
M_C_DQS_DP_1: DIMMC1.164(DQS1_DP) DIMMC2.164(DQS1_DP) ; also on sheet 135
M_C_DQS_DP_2: DIMMC1.175(DQS2_DP) DIMMC2.175(DQS2_DP) ; also on sheet 135
M_C_DQS_DP_3: DIMMC1.186(DQS3_DP) DIMMC2.186(DQS3_DP) ; also on sheet 135
M_C_DQS_DP_4: DIMMC1.245(DQS4_DP) DIMMC2.245(DQS4_DP) ; also on sheet 135
M_C_DQS_DP_5: DIMMC1.256(DQS5_DP) DIMMC2.256(DQS5_DP) ; also on sheet 135
M_C_DQS_DP_6: DIMMC1.267(DQS6_DP) DIMMC2.267(DQS6_DP) ; also on sheet 135
M_C_DQS_DP_7: DIMMC1.278(DQS7_DP) DIMMC2.278(DQS7_DP) ; also on sheet 135
M_C_DQS_DP_8: DIMMC1.197(DQS8_DP) DIMMC2.197(DQS8_DP) ; also on sheet 135
M_C_DQS_DP_9: DIMMC1.7(DQS9_DP) DIMMC2.7(DQS9_DP) ; also on sheet 135
M_C_DQS_DP_10: DIMMC1.18(DQS10_DP) DIMMC2.18(DQS10_DP) ; also on sheet 135
M_C_DQS_DP_11: DIMMC1.29(DQS11_DP) DIMMC2.29(DQS11_DP) ; also on sheet 135
M_C_DQS_DP_12: DIMMC1.40(DQS12_DP) DIMMC2.40(DQS12_DP) ; also on sheet 135
M_C_DQS_DP_13: DIMMC1.99(DQS13_DP) DIMMC2.99(DQS13_DP) ; also on sheet 135
M_C_DQS_DP_14: DIMMC1.110(DQS14_DP) DIMMC2.110(DQS14_DP) ; also on sheet 135
M_C_DQS_DP_15: DIMMC1.121(DQS15_DP) DIMMC2.121(DQS15_DP) ; also on sheet 135
M_C_DQS_DP_16: DIMMC1.132(DQS16_DP) DIMMC2.132(DQS16_DP) ; also on sheet 135
M_C_DQS_DP_17: DIMMC1.51(DQS17_DP) DIMMC2.51(DQS17_DP) ; also on sheet 135
M_C_ECC_0: DIMMC1.49(CB0) DIMMC2.49(CB0) ; also on sheet 135
M_C_ECC_1: DIMMC1.194(CB1) DIMMC2.194(CB1) ; also on sheet 135
M_C_ECC_2: DIMMC1.56(CB2) DIMMC2.56(CB2) ; also on sheet 135
M_C_ECC_3: DIMMC1.201(CB3) DIMMC2.201(CB3) ; also on sheet 135
M_C_ECC_4: DIMMC1.47(CB4) DIMMC2.47(CB4) ; also on sheet 135
M_C_ECC_5: DIMMC1.192(CB5) DIMMC2.192(CB5) ; also on sheet 135
M_C_ECC_6: DIMMC1.54(CB6) DIMMC2.54(CB6) ; also on sheet 135
M_C_ECC_7: DIMMC1.199(CB7) DIMMC2.199(CB7) ; also on sheet 135
M_C_MA_0: DIMMC1.79(A0) DIMMC2.79(A0) ; also on sheet 135
M_C_MA_1: DIMMC1.72(A1) DIMMC2.72(A1) ; also on sheet 135
M_C_MA_2: DIMMC1.216(A2) DIMMC2.216(A2) ; also on sheet 135
M_C_MA_3: DIMMC1.71(A3) DIMMC2.71(A3) ; also on sheet 135
M_C_MA_4: DIMMC1.214(A4) DIMMC2.214(A4) ; also on sheet 135
M_C_MA_5: DIMMC1.213(A5) DIMMC2.213(A5) ; also on sheet 135
M_C_MA_6: DIMMC1.69(A6) DIMMC2.69(A6) ; also on sheet 135
M_C_MA_7: DIMMC1.211(A7) DIMMC2.211(A7) ; also on sheet 135
M_C_MA_8: DIMMC1.68(A8) DIMMC2.68(A8) ; also on sheet 135
M_C_MA_9: DIMMC1.66(A9) DIMMC2.66(A9) ; also on sheet 135
M_C_MA_10: DIMMC1.225(A10) DIMMC2.225(A10) ; also on sheet 135
M_C_MA_11: DIMMC1.210(A11) DIMMC2.210(A11) ; also on sheet 135
M_C_MA_12: DIMMC1.65(A12) DIMMC2.65(A12) ; also on sheet 135
M_C_MA_13: DIMMC1.232(A13) DIMMC2.232(A13) ; also on sheet 135
M_C_MA_14: DIMMC1.228(A14/WE#) DIMMC2.228(A14/WE#) ; also on sheet 135
M_C_MA_15: DIMMC1.86(A15/CAS#) DIMMC2.86(A15/CAS#) ; also on sheet 135
M_C_MA_16: DIMMC1.82(A16/RAS#) DIMMC2.82(A16/RAS#) ; also on sheet 135
M_C_MA_17: DIMMC1.234(A17) DIMMC2.234(A17) ; also on sheet 135
M_C_ODT_0: DIMMC1.87(ODT0) ; also on sheet 135
M_C_ODT_1: DIMMC1.91(ODT1) ; also on sheet 135
M_C_ODT_2: DIMMC2.87(ODT0) ; also on sheet 135
M_C_ODT_3: DIMMC2.91(ODT1) ; also on sheet 135
M_C_PAR: DIMMC1.222(PAR) DIMMC2.222(PAR) ; also on sheet 135
M_CD_RESET_N: DIMMC1.58(RESET#) DIMMC2.58(RESET#) DIMMD1.58(RESET#) ; also on sheet 112 139
M_CD_VREF: C869.1 C870.1 C872.1 DIMMC1.146(VREFCA) DIMMC2.146(VREFCA) DIMMD1.146(VREFCA) ; also on sheet 112 139
M_D_ACT_N: DIMMD1.62(ACT#) ; also on sheet 112 134
M_D_ALERT_N: DIMMD1.208(ALERT#) ; also on sheet 112 134
M_D_BA_0: DIMMD1.81(BA0) ; also on sheet 112 134
M_D_BA_1: DIMMD1.224(BA1) ; also on sheet 112 134
M_D_BG_0: DIMMD1.63(BG0) ; also on sheet 112 134
M_D_BG_1: DIMMD1.207(BG1) ; also on sheet 112 134
M_D_C_2: DIMMD1.235(C2) ; also on sheet 112 134
M_D_CKE_0: DIMMD1.60(CKE0) ; also on sheet 134
M_D_CKE_1: DIMMD1.203(CKE1) ; also on sheet 134
M_D_CLK_DN_0: DIMMD1.75(CK0_DN) ; also on sheet 134
M_D_CLK_DN_2: DIMMD1.219(CK1_DN) ; also on sheet 134
M_D_CLK_DP_0: DIMMD1.74(CK0_DP) ; also on sheet 134
M_D_CLK_DP_2: DIMMD1.218(CK1_DP) ; also on sheet 134
M_D_CS_N_0: DIMMD1.84(S0#) ; also on sheet 134
M_D_CS_N_1: DIMMD1.89(S1#) ; also on sheet 134
M_D_CS_N_2: DIMMD1.93(S2_N_C0) ; also on sheet 134
M_D_CS_N_3: DIMMD1.237(S3_N_C1) ; also on sheet 134
M_D_DQ_0: DIMMD1.5(DQ_0) ; also on sheet 112 134
M_D_DQ_1: DIMMD1.150(DQ_1) ; also on sheet 112 134
M_D_DQ_2: DIMMD1.12(DQ_2) ; also on sheet 112 134
M_D_DQ_3: DIMMD1.157(DQ_3) ; also on sheet 112 134
M_D_DQ_4: DIMMD1.3(DQ_4) ; also on sheet 112 134
M_D_DQ_5: DIMMD1.148(DQ_5) ; also on sheet 112 134
M_D_DQ_6: DIMMD1.10(DQ_6) ; also on sheet 112 134
M_D_DQ_7: DIMMD1.155(DQ_7) ; also on sheet 112 134
M_D_DQ_8: DIMMD1.16(DQ_8) ; also on sheet 112 134
M_D_DQ_9: DIMMD1.161(DQ_9) ; also on sheet 112 134
M_D_DQ_10: DIMMD1.23(DQ_10) ; also on sheet 112 134
M_D_DQ_11: DIMMD1.168(DQ_11) ; also on sheet 112 134
M_D_DQ_12: DIMMD1.14(DQ_12) ; also on sheet 112 134
M_D_DQ_13: DIMMD1.159(DQ_13) ; also on sheet 112 134
M_D_DQ_14: DIMMD1.21(DQ_14) ; also on sheet 112 134
M_D_DQ_15: DIMMD1.166(DQ_15) ; also on sheet 112 134
M_D_DQ_16: DIMMD1.27(DQ_16) ; also on sheet 112 134
M_D_DQ_17: DIMMD1.172(DQ_17) ; also on sheet 112 134
M_D_DQ_18: DIMMD1.34(DQ_18) ; also on sheet 112 134
M_D_DQ_19: DIMMD1.179(DQ_19) ; also on sheet 112 134
M_D_DQ_20: DIMMD1.25(DQ_20) ; also on sheet 112 134
M_D_DQ_21: DIMMD1.170(DQ_21) ; also on sheet 112 134
M_D_DQ_22: DIMMD1.32(DQ_22) ; also on sheet 112 134
M_D_DQ_23: DIMMD1.177(DQ_23) ; also on sheet 112 134
M_D_DQ_24: DIMMD1.38(DQ_24) ; also on sheet 112 134
M_D_DQ_25: DIMMD1.183(DQ_25) ; also on sheet 112 134
M_D_DQ_26: DIMMD1.45(DQ_26) ; also on sheet 112 134
M_D_DQ_27: DIMMD1.190(DQ_27) ; also on sheet 112 134
M_D_DQ_28: DIMMD1.36(DQ_28) ; also on sheet 112 134
M_D_DQ_29: DIMMD1.181(DQ_29) ; also on sheet 112 134
M_D_DQ_30: DIMMD1.43(DQ_30) ; also on sheet 112 134
M_D_DQ_31: DIMMD1.188(DQ_31) ; also on sheet 112 134
M_D_DQ_32: DIMMD1.97(DQ_32) ; also on sheet 112 134
M_D_DQ_33: DIMMD1.242(DQ_33) ; also on sheet 112 134
M_D_DQ_34: DIMMD1.104(DQ_34) ; also on sheet 112 134
M_D_DQ_35: DIMMD1.249(DQ_35) ; also on sheet 112 134
M_D_DQ_36: DIMMD1.95(DQ_36) ; also on sheet 112 134
M_D_DQ_37: DIMMD1.240(DQ_37) ; also on sheet 112 134
M_D_DQ_38: DIMMD1.102(DQ_38) ; also on sheet 112 134
M_D_DQ_39: DIMMD1.247(DQ_39) ; also on sheet 112 134
M_D_DQ_40: DIMMD1.108(DQ_40) ; also on sheet 112 134
M_D_DQ_41: DIMMD1.253(DQ_41) ; also on sheet 112 134
M_D_DQ_42: DIMMD1.115(DQ_42) ; also on sheet 112 134
M_D_DQ_43: DIMMD1.260(DQ_43) ; also on sheet 112 134
M_D_DQ_44: DIMMD1.106(DQ_44) ; also on sheet 112 134
M_D_DQ_45: DIMMD1.251(DQ_45) ; also on sheet 112 134
M_D_DQ_46: DIMMD1.113(DQ_46) ; also on sheet 112 134
M_D_DQ_47: DIMMD1.258(DQ_47) ; also on sheet 112 134
M_D_DQ_48: DIMMD1.119(DQ_48) ; also on sheet 112 134
M_D_DQ_49: DIMMD1.264(DQ_49) ; also on sheet 112 134
M_D_DQ_50: DIMMD1.126(DQ_50) ; also on sheet 112 134
M_D_DQ_51: DIMMD1.271(DQ_51) ; also on sheet 112 134
M_D_DQ_52: DIMMD1.117(DQ_52) ; also on sheet 112 134
M_D_DQ_53: DIMMD1.262(DQ_53) ; also on sheet 112 134
M_D_DQ_54: DIMMD1.124(DQ_54) ; also on sheet 112 134
M_D_DQ_55: DIMMD1.269(DQ_55) ; also on sheet 112 134
M_D_DQ_56: DIMMD1.130(DQ_56) ; also on sheet 112 134
M_D_DQ_57: DIMMD1.275(DQ_57) ; also on sheet 112 134
M_D_DQ_58: DIMMD1.137(DQ_58) ; also on sheet 112 134
M_D_DQ_59: DIMMD1.282(DQ_59) ; also on sheet 112 134
M_D_DQ_60: DIMMD1.128(DQ_60) ; also on sheet 112 134
M_D_DQ_61: DIMMD1.273(DQ_61) ; also on sheet 112 134
M_D_DQ_62: DIMMD1.135(DQ_62) ; also on sheet 112 134
M_D_DQ_63: DIMMD1.280(DQ_63) ; also on sheet 112 134
M_D_DQS_DN_0: DIMMD1.152(DQS0_DN) ; also on sheet 112 134
M_D_DQS_DN_1: DIMMD1.163(DQS1_DN) ; also on sheet 112 134
M_D_DQS_DN_2: DIMMD1.174(DQS2_DN) ; also on sheet 112 134
M_D_DQS_DN_3: DIMMD1.185(DQS3_DN) ; also on sheet 112 134
M_D_DQS_DN_4: DIMMD1.244(DQS4_DN) ; also on sheet 112 134
M_D_DQS_DN_5: DIMMD1.255(DQS5_DN) ; also on sheet 112 134
M_D_DQS_DN_6: DIMMD1.266(DQS6_DN) ; also on sheet 112 134
M_D_DQS_DN_7: DIMMD1.277(DQS7_DN) ; also on sheet 112 134
M_D_DQS_DN_8: DIMMD1.196(DQS8_DN) ; also on sheet 112 134
M_D_DQS_DN_9: DIMMD1.8(DQS9_DN) ; also on sheet 112 134
M_D_DQS_DN_10: DIMMD1.19(DQS10_DN) ; also on sheet 112 134
M_D_DQS_DN_11: DIMMD1.30(DQS11_DN) ; also on sheet 112 134
M_D_DQS_DN_12: DIMMD1.41(DQS12_DN) ; also on sheet 112 134
M_D_DQS_DN_13: DIMMD1.100(DQS13_DN) ; also on sheet 112 134
M_D_DQS_DN_14: DIMMD1.111(DQS14_DN) ; also on sheet 112 134
M_D_DQS_DN_15: DIMMD1.122(DQS15_DN) ; also on sheet 112 134
M_D_DQS_DN_16: DIMMD1.133(DQS16_DN) ; also on sheet 112 134
M_D_DQS_DN_17: DIMMD1.52(DQS17_DN) ; also on sheet 112 134
M_D_DQS_DP_0: DIMMD1.153(DQS0_DP) ; also on sheet 112 134
M_D_DQS_DP_1: DIMMD1.164(DQS1_DP) ; also on sheet 112 134
M_D_DQS_DP_2: DIMMD1.175(DQS2_DP) ; also on sheet 112 134
M_D_DQS_DP_3: DIMMD1.186(DQS3_DP) ; also on sheet 112 134
M_D_DQS_DP_4: DIMMD1.245(DQS4_DP) ; also on sheet 112 134
M_D_DQS_DP_5: DIMMD1.256(DQS5_DP) ; also on sheet 112 134
M_D_DQS_DP_6: DIMMD1.267(DQS6_DP) ; also on sheet 112 134
M_D_DQS_DP_7: DIMMD1.278(DQS7_DP) ; also on sheet 112 134
M_D_DQS_DP_8: DIMMD1.197(DQS8_DP) ; also on sheet 112 134
M_D_DQS_DP_9: DIMMD1.7(DQS9_DP) ; also on sheet 112 134
M_D_DQS_DP_10: DIMMD1.18(DQS10_DP) ; also on sheet 112 134
M_D_DQS_DP_11: DIMMD1.29(DQS11_DP) ; also on sheet 112 134
M_D_DQS_DP_12: DIMMD1.40(DQS12_DP) ; also on sheet 112 134
M_D_DQS_DP_13: DIMMD1.99(DQS13_DP) ; also on sheet 112 134
M_D_DQS_DP_14: DIMMD1.110(DQS14_DP) ; also on sheet 112 134
M_D_DQS_DP_15: DIMMD1.121(DQS15_DP) ; also on sheet 112 134
M_D_DQS_DP_16: DIMMD1.132(DQS16_DP) ; also on sheet 112 134
M_D_DQS_DP_17: DIMMD1.51(DQS17_DP) ; also on sheet 112 134
M_D_ECC_0: DIMMD1.49(CB0) ; also on sheet 112 134
M_D_ECC_1: DIMMD1.194(CB1) ; also on sheet 112 134
M_D_ECC_2: DIMMD1.56(CB2) ; also on sheet 112 134
M_D_ECC_3: DIMMD1.201(CB3) ; also on sheet 112 134
M_D_ECC_4: DIMMD1.47(CB4) ; also on sheet 112 134
M_D_ECC_5: DIMMD1.192(CB5) ; also on sheet 112 134
M_D_ECC_6: DIMMD1.54(CB6) ; also on sheet 112 134
M_D_ECC_7: DIMMD1.199(CB7) ; also on sheet 112 134
M_D_MA_0: DIMMD1.79(A0) ; also on sheet 112 134
M_D_MA_1: DIMMD1.72(A1) ; also on sheet 112 134
M_D_MA_2: DIMMD1.216(A2) ; also on sheet 112 134
M_D_MA_3: DIMMD1.71(A3) ; also on sheet 112 134
M_D_MA_4: DIMMD1.214(A4) ; also on sheet 112 134
M_D_MA_5: DIMMD1.213(A5) ; also on sheet 112 134
M_D_MA_6: DIMMD1.69(A6) ; also on sheet 112 134
M_D_MA_7: DIMMD1.211(A7) ; also on sheet 112 134
M_D_MA_8: DIMMD1.68(A8) ; also on sheet 112 134
M_D_MA_9: DIMMD1.66(A9) ; also on sheet 112 134
M_D_MA_10: DIMMD1.225(A10) ; also on sheet 112 134
M_D_MA_11: DIMMD1.210(A11) ; also on sheet 112 134
M_D_MA_12: DIMMD1.65(A12) ; also on sheet 112 134
M_D_MA_13: DIMMD1.232(A13) ; also on sheet 112 134
M_D_MA_14: DIMMD1.228(A14/WE#) ; also on sheet 112 134
M_D_MA_15: DIMMD1.86(A15/CAS#) ; also on sheet 112 134
M_D_MA_16: DIMMD1.82(A16/RAS#) ; also on sheet 112 134
M_D_MA_17: DIMMD1.234(A17) ; also on sheet 112 134
M_D_ODT_0: DIMMD1.87(ODT0) ; also on sheet 134
M_D_ODT_1: DIMMD1.91(ODT1) ; also on sheet 134
M_D_PAR: DIMMD1.222(PAR) ; also on sheet 112 134
NV_SAVE_CHC_DIMM0: DIMMC1.230(RFU_2) ; also on sheet 52
NV_SAVE_CHC_DIMM1: DIMMC2.230(RFU_2) ; also on sheet 52
NV_SAVE_CHD_DIMM0: DIMMD1.230(RFU_2) ; also on sheet 52
PVPP_CD: DIMMC1.142(VPP_0) DIMMC1.143(VPP_1) DIMMC1.284(VDDSPD) DIMMC1.286(VPP_2) DIMMC1.287(VPP_3) DIMMC1.288(VPP_4) DIMMC2.139(SA0) DIMMC2.142(VPP_0) DIMMC2.143(VPP_1) DIMMC2.284(VDDSPD) DIMMC2.286(VPP_2) DIMMC2.287(VPP_3) DIMMC2.288(VPP_4) DIMMD1.142(VPP_0) DIMMD1.143(VPP_1) DIMMD1.238(SA2) DIMMD1.284(VDDSPD) DIMMD1.286(VPP_2) DIMMD1.287(VPP_3) DIMMD1.288(VPP_4) ; also on sheet 22 112 160
PVTT_CD: DIMMC1.77(VTT_0) DIMMC1.221(VTT_1) DIMMC2.77(VTT_0) DIMMC2.221(VTT_1) DIMMD1.77(VTT_0) DIMMD1.221(VTT_1) ; also on sheet 24 112
SMB_DDR_CD_SCL_LVC2V5: DIMMC1.141(SCL) DIMMC2.141(SCL) DIMMD1.141(SCL) ; also on sheet 112 160
SMB_DDR_CD_SDA_LVC2V5: DIMMC1.285(SDA) DIMMC2.285(SDA) DIMMD1.285(SDA) ; also on sheet 112 160

Not connected (* = marked no-connect by the designer): DIMMC1 144(RFU_3)* 205(RFU_0)* 227(RFU_1)* NP1* NP2* NP3*; DIMMC2 144(RFU_3)* 205(RFU_0)* 227(RFU_1)* NP1* NP2* NP3*; DIMMD1 144(RFU_3)* 205(RFU_0)* 227(RFU_1)* NP1* NP2* NP3*

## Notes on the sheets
sheet 113
- DDR4 DIMM CPU0 CHD-1
- FAB1 REV021 20150424
- FAB1 REV003 20150318
- DIMMD1
- I2C Address = A8
- Chip Select Signal DIMM Mapping
- ODT Signal DIMM Mapping
- CKE Signal DIMM Mapping
- DDR4 Clock Signal DIMM Pin Mapping (UDIMM/RDIMM support)
- DIMM
- DIMM Pin
- CPU Signal
- DIMM
- DIMM Pin
- CPU Signal
- DIMM
- DIMM Pin
- CPU Signal
- DIMM
- DIMM Pin
- CPU Signal
- DIMM0
- 83
- CS_N0
- DIMM0
- 86
- ODT0
- DIMM0
- 59
- CKE0
- DIMM0
- 73
- CLK_DP0
- DIMM0
- 88
- CS_N1
- DIMM0
- 90
- ODT1
- DIMM0
- 200
- CKE1
- DIMM0
- 74
- CLK_DN0
- DIMM0
- 92
- CS_N2/C[0]
- DIMM1
- 86
- ODT2
- DIMM1
- 59
- CKE2
- DIMM0
- 215
- CLK_DP2
- DIMM0
- 234
- CS_N3/C[1]
- DIMM1
- 90
- ODT3
- DIMM1
- 200
- CKE3
- DIMM0
- 216
- CLK_DN2
- DIMM1
- 83
- CS_N4
- DIMM1
- 73
- CLK_DP1
- DIMM1
- 88
- CS_N5
- DIMM1
- 74
- CLK_DN1
- DIMM1
- 92
- CS_N6/C[3]
- DIMM1
- 215
- CLK_DP3
- DIMM1
- 234
- CS_N7/C[4]
- DIMM1
- 216
- CLK_DN3
sheet 114
- DDR4 DIMM CPU0 CHC-2
- FAB1 REV021 20150424
- FAB1 REV003 20150318
- DIMMC2
- I2C Address = A2
- Chip Select Signal DIMM Mapping
- ODT Signal DIMM Mapping
- CKE Signal DIMM Mapping
- DDR4 Clock Signal DIMM Pin Mapping (UDIMM/RDIMM support)
- DIMM
- DIMM Pin
- CPU Signal
- DIMM
- DIMM Pin
- CPU Signal
- DIMM
- DIMM Pin
- CPU Signal
- DIMM
- DIMM Pin
- CPU Signal
- DIMM0
- 83
- CS_N0
- DIMM0
- 86
- ODT0
- DIMM0
- 59
- CKE0
- DIMM0
- 73
- CLK_DP0
- DIMM0
- 88
- CS_N1
- DIMM0
- 90
- ODT1
- DIMM0
- 200
- CKE1
- DIMM0
- 74
- CLK_DN0
- DIMM0
- 92
- CS_N2/C[0]
- DIMM1
- 86
- ODT2
- DIMM1
- 59
- CKE2
- DIMM0
- 215
- CLK_DP2
- DIMM0
- 234
- CS_N3/C[1]
- DIMM1
- 90
- ODT3
- DIMM1
- 200
- CKE3
- DIMM0
- 216
- CLK_DN2
- DIMM1
- 83
- CS_N4
- DIMM1
- 73
- CLK_DP1
- DIMM1
- 88
- CS_N5
- DIMM1
- 74
- CLK_DN1
- DIMM1
- 92
- CS_N6/C[3]
- DIMM1
- 215
- CLK_DP3
- DIMM1
- 234
- CS_N7/C[4]
- DIMM1
- 216
- CLK_DN3
sheet 115
- DDR4 DIMM CPU0 CHC-1
- FAB1 REV021 20150424
- FAB1 REV003 20150318
- DIMMC1
- I2C Address = A0
- Chip Select Signal DIMM Mapping
- ODT Signal DIMM Mapping
- CKE Signal DIMM Mapping
- DDR4 Clock Signal DIMM Pin Mapping (UDIMM/RDIMM support)
- DIMM
- DIMM Pin
- CPU Signal
- DIMM
- DIMM Pin
- CPU Signal
- DIMM
- DIMM Pin
- CPU Signal
- DIMM
- DIMM Pin
- CPU Signal
- DIMM0
- 83
- CS_N0
- DIMM0
- 86
- ODT0
- DIMM0
- 59
- CKE0
- DIMM0
- 73
- CLK_DP0
- DIMM0
- 88
- CS_N1
- DIMM0
- 90
- ODT1
- DIMM0
- 200
- CKE1
- DIMM0
- 74
- CLK_DN0
- DIMM0
- 92
- CS_N2/C[0]
- DIMM1
- 86
- ODT2
- DIMM1
- 59
- CKE2
- DIMM0
- 215
- CLK_DP2
- DIMM0
- 234
- CS_N3/C[1]
- DIMM1
- 90
- ODT3
- DIMM1
- 200
- CKE3
- DIMM0
- 216
- CLK_DN2
- DIMM1
- 83
- CS_N4
- DIMM1
- 73
- CLK_DP1
- DIMM1
- 88
- CS_N5
- DIMM1
- 74
- CLK_DN1
- DIMM1
- 92
- CS_N6/C[3]
- DIMM1
- 215
- CLK_DP3
- DIMM1
- 234
- CS_N7/C[4]
- DIMM1
- 216
- CLK_DN3
